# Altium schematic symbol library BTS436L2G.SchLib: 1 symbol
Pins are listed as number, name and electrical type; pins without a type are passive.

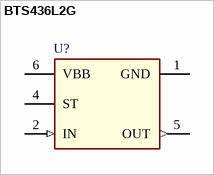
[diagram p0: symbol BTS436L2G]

## BTS436L2G
designator U?  (value not drawn)
Smart High-Side Power Switch, VBB 43V; Manufacturer: Infineon Technologies
footprint TO170P1500X450-6_5N
pins: 1 GND (power) "Logic Ground", 2 IN (in) "Input", 4 ST (oc) "Diagnostic Feedback", 5 OUT (out) "Output", 6 VBB (power) "Positive Power Supply Voltage"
